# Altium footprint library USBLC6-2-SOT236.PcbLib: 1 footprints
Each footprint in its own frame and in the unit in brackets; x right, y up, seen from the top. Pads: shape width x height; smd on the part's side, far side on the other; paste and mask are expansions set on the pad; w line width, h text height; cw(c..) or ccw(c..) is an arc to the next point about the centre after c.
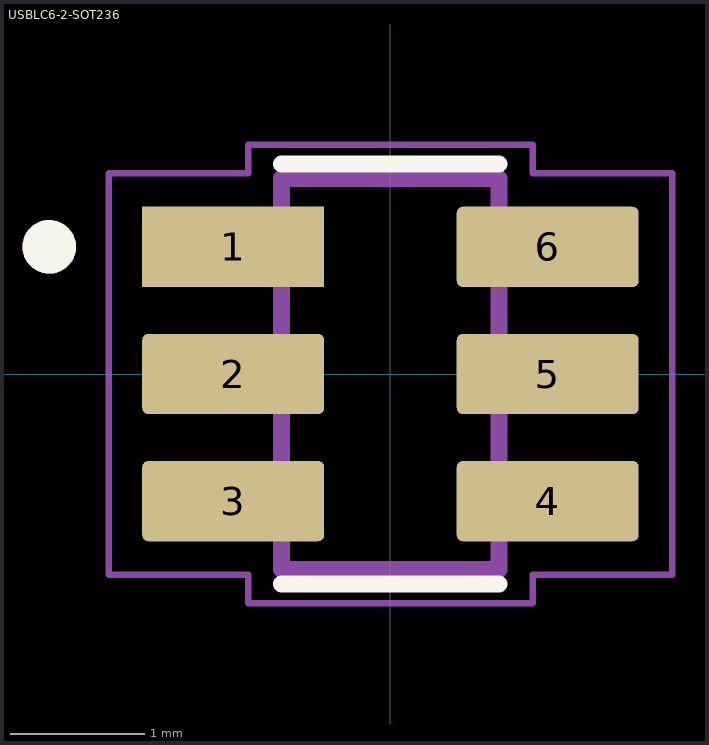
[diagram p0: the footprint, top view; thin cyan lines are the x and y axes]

## USBLC6-2-SOT236 [mm]
pads (6):
  rect 1.36x0.6 smd: 1(-1.175,0.95)
  rrect15% 1.36x0.6 smd: 2(-1.175,0) 3(-1.175,-0.95) 4(1.175,-0.95) 5(1.175,0) 6(1.175,0.95)
Top Overlay:
  circle w0.2: c-2.55,0.95 r0.1
  lines w0.127: -0.813,-1.57 0.813,-1.57 ; -0.813,1.57 0.813,1.57
Mechanical 13:
  circle w0.2: c-2.55,0.95 r0.1
  lines w0.127: -0.813,-1.462 0.813,-1.462 0.813,1.462 -0.813,1.462 -0.813,-1.462
Mechanical 15:
  lines w0.05: -2.105,-1.5 -1.062,-1.5 -1.062,-1.713 1.062,-1.713 1.062,-1.5 2.105,-1.5 2.105,1.5 1.062,1.5 1.062,1.713 -1.062,1.713 -1.062,1.5 -2.105,1.5 -2.105,-1.5
3D body "USBLC6-2-SOT236.STEP": height 1.42, standoff -0.03, extent -1.398,-1.466 1.402,1.459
